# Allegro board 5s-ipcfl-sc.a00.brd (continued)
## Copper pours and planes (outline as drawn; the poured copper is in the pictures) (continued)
VRM_PWM4_SW_C on BOTTOM (solid shape): 61.41,147.55 61.41,147 61.84,146.57 62.99,146.57 63.52,147.09 64.21,147.09 64.59,147.48 69.82,147.48 70.87,146.43 70.87,141.1 68.96,139.19 67.06,139.19 66.8,139.45 66.8,141.1 66.29,141.6 54.94,141.6 54.59,141.95 54.59,142.2 69.98,142.2 69.98,144.8 67.39,144.8 67.39,142.2 54.59,142.2 54.59,147.37 55.07,147.85 61.1,147.85
VRM_PWM4_SW_C on VCC (solid shape): 61.34,148.59 61.34,147.19 61.36,147.1 61.42,147.01 61.8,146.63 61.88,146.58 61.98,146.56 62.87,146.56 62.96,146.58 63.04,146.63 63.86,147.45 69.87,147.45 70.87,146.45 70.87,141.08 68.98,139.19 66.91,139.19 66.8,139.3 66.8,140.97 66.78,141.07 66.73,141.15 66.35,141.53 66.26,141.59 66.17,141.6 54.36,141.6 54.36,148.48 54.59,148.72 61.21,148.72
N27670502 on TOP (solid shape): 64.64,10.29 64.64,6.96 64.14,6.45 64.05,6.45 64.03,6.46 63.48,6.66 62.94,6.45 62.36,6.45 62.05,6.76 62.05,8.31 61.98,8.38 61.98,8.71 62.41,8.71 62.41,9.32 61.98,9.32 61.98,10.54 62.29,10.86 64.07,10.86
N30429432 on TOP (solid shape): 221.39,211.73 221.39,206.4 219.23,204.24 219.23,201.96 218.85,201.57 214.53,201.57 213.77,202.34 211.86,202.34 211.68,202.51 211.68,208.48 214.63,208.48 214.63,210.1 213,210.1 213,208.48 211.68,208.48 211.68,211.56 211.94,211.81 213,211.81 213.01,211.72 213.02,211.64 213.04,211.56 213.06,211.48 213.1,211.41 213.14,211.34 213.19,211.28 213.24,211.21 213.3,211.16 213.37,211.11 213.44,211.07 213.51,211.04 213.59,211.01 213.67,210.99 213.75,210.98 213.83,210.98 213.91,210.98 213.99,211 214.07,211.02 214.14,211.05 214.22,211.08 214.29,211.13 214.35,211.18 214.41,211.23 214.46,211.29 214.51,211.36 214.55,211.43 214.58,211.51 214.6,211.58 214.62,211.66 214.63,211.74 214.63,211.83 214.62,211.91 214.61,211.99 214.58,212.06 214.56,212.14 214.57,212.17 214.58,212.2 214.6,212.22 214.62,212.23 214.66,212.24 220.88,212.24
N30429432 on BOTTOM (solid shape): 219.07,207.52 219.07,201.93 218.69,201.55 214.76,201.55 213.61,202.69 213.61,208.03 213.43,208.21 213.43,208.33 213.49,208.39 214.72,208.39 214.72,210.19 213.06,210.19 213.06,210.41 213.48,210.82 215.77,210.82
N31341317 on TOP (solid shape): outline of 226 points within 156.46,10.41 168.66,17.53
N31341317 on TOP (solid shape): outline of 241 points within 161.54,10.41 168.66,17.53
N31341317 on BOTTOM (solid shape): outline of 241 points within 161.54,10.41 168.66,17.53

Small or netless copper shapes (teardrops, artwork), in the pictures only: 3113 on TOP, 3234 on BOTTOM, 2 on VCC

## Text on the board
BOTTOM: list("[Spacing-SameNet] BOTTOM" "48.Thru Pin to SMD Pin Same Net" "5 MIL [DEFAULT]" "OVERLAP" "" "DRC ERROR CLASS/BOTTOM" "[ThruPin] +12V_CPU (<uTiL>cId3330<uTiL>.1) (2143.9 8555.0)" "[SmdPin] +12V_CPU (<uTiL>cId4743<uTiL>.2) (2182.5 8556.0)" list(2168.000000 8540.000000) nil)@@@list("amy_chou" "2017/07/21 16:08:01" nil "P143000034-PC" "5s-ipcfl-sc.a00")@@@list("iris_chen" "2017/07/24 16:08:43" nil "p16c000357-pc" "5s-ipcfl-sc.a00") | list("[Spacing] BOTTOM" "30.Test Pin to No Probe" "0 MIL [DEFAULT]" "0 MIL" "0.00 MIL" "DRC ERROR CLASS/BOTTOM" "[ThruPin] VRM_PWM2_SW_C (<uTiL>cId2857<uTiL>.1) (2699.14 7688.63)" "[Shape] Manufacturing/No_Probe_Bottom ((2738.19 7647.19) (2851.81 7722.81))" list(2744.140000 7647.190000) nil)@@@list("amy_chou" "2017/07/21 16:05:34" nil "P143000034-PC" "5s-ipcfl-sc.a00")@@@list("iris_chen" "2017/07/24 16:08:08" nil "p16c000357-pc" "5s-ipcfl-sc.a00") | list("[Spacing] BOTTOM" "31.Test Pin to No Probe" "0 MIL [DEFAULT]" "0 MIL" "0.00 MIL" "DRC ERROR CLASS/BOTTOM" "[ThruPin] VRM_PWM1_SW_C (<uTiL>cId2858<uTiL>.1) (2699.14 6995.63)" "[Shape] Manufacturing/No_Probe_Bottom ((2735.19 6962.19) (2848.81 7037.81))" list(2744.140000 6962.190000) nil)@@@list("amy_chou" "2017/07/21 16:05:39" nil "P143000034-PC" "5s-ipcfl-sc.a00")@@@list("iris_chen" "2017/07/24 16:08:09" nil "p16c000357-pc" "5s-ipcfl-sc.a00") | list("[Spacing] BOTTOM" "25.Test Pin to No Probe" "0 MIL [(20)]" "0 MIL" "0.00 MIL" "DRC ERROR CLASS/BOTTOM" "[ThruPin] VRM_PWM3_SW_C (<uTiL>cId2856<uTiL>.1) (2699.14 6302.63)" "[Shape] Manufacturing/No_Probe_Bottom ((2728.19 6262.19) (2841.81 6337.81))" list(2744.140000 6262.190000) nil)@@@list("amy_chou" "2017/07/21 16:05:32" nil "P143000034-PC" "5s-ipcfl-sc.a00")@@@list("iris_chen" "2017/07/24 16:08:01" nil "p16c000357-pc" "5s-ipcfl-sc.a00") | list("[Spacing] BOTTOM" "28.Test Pin to No Probe" "0 MIL [(20)]" "0 MIL" "0.00 MIL" "DRC ERROR CLASS/BOTTOM" "[ThruPin] VRM_PWM4_SW_C (<uTiL>cId2855<uTiL>.1) (2704.14 5649.63)" "[Shape] Manufacturing/No_Probe_Bottom ((2741.19 5612.19) (2854.81 5687.81))" list(2749.140000 5612.190000) nil)@@@list("amy_chou" "2017/07/21 16:05:36" nil "P143000034-PC" "5s-ipcfl-sc.a00")@@@list("iris_chen" "2017/07/24 16:08:05" nil "p16c000357-pc" "5s-ipcfl-sc.a00") | list("[Physical] BOTTOM" "406.Pad/Pad Direct Connect" "NOT_ALLOWED [(PWR_20)]" "ALL_ALLOWED" "" "DRC ERROR CLASS/BOTTOM" "[ThruPin] +VCORE (<uTiL>cId2857<uTiL>.2) (2966.86 7767.37)" "[SmdPin] +VCORE (<uTiL>cId2869<uTiL>.1) (2904.5 7765.0)" list(2904.500000 7765.000000) nil)@@@list("amy_chou" "2017/07/21 16:11:35" nil "P143000034-PC" "5s-ipcfl-sc.a00")@@@list("iris_chen" "2017/07/24 16:23:35" nil "p16c000357-pc" "5s-ipcfl-sc.a00") | list("[Physical] BOTTOM" "408.Pad/Pad Direct Connect" "NOT_ALLOWED [(PWR_20)]" "ALL_ALLOWED" "" "DRC ERROR CLASS/BOTTOM" "[ThruPin] +VCORE (<uTiL>cId2856<uTiL>.2) (2966.86 6381.37)" "[SmdPin] +VCORE (<uTiL>cId332<uTiL>.1) (2905.5 6375.0)" list(2905.500000 6375.000000) nil)@@@list("amy_chou" "2017/07/21 16:11:34" nil "P143000034-PC" "5s-ipcfl-sc.a00")@@@list("iris_chen" "2017/07/24 16:23:37" nil "p16c000357-pc" "5s-ipcfl-sc.a00") | list("[Spacing-SameNet] BOTTOM" "51.Thru Pin to SMD Pin Same Net" "5 MIL [DEFAULT]" "OVERLAP" "" "DRC ERROR CLASS/BOTTOM" "[ThruPin] +VCORE (<uTiL>cId2855<uTiL>.2) (2971.86 5728.37)" "[SmdPin] +VCORE (<uTiL>cId683<uTiL>.1) (2900.5 5729.0)" list(2909.390000 5724.700000) nil)@@@list("amy_chou" "2017/07/21 16:08:03" nil "P143000034-PC" "5s-ipcfl-sc.a00")@@@list("iris_chen" "2017/07/24 16:08:53" nil "p16c000357-pc" "5s-ipcfl-sc.a00") | list("[Physical] BOTTOM" "407.Pad/Pad Direct Connect" "NOT_ALLOWED [(PWR_20)]" "ALL_ALLOWED" "" "DRC ERROR CLASS/BOTTOM" "[ThruPin] +VCORE (<uTiL>cId2858<uTiL>.2) (2966.86 7074.37)" "[SmdPin] +VCORE (<uTiL>cId2871<uTiL>.1) (2915.5 7070.0)" list(2915.500000 7070.000000) nil)@@@list("amy_chou" "2017/07/21 16:11:34" nil "P143000034-PC" "5s-ipcfl-sc.a00")@@@list("iris_chen" "2017/07/24 16:23:36" nil "p16c000357-pc" "5s-ipcfl-sc.a00") | list("[Physical] BOTTOM" "409.Pad/Pad Direct Connect" "NOT_ALLOWED [(PWR_20)]" "ALL_ALLOWED" "" "DRC ERROR CLASS/BOTTOM" "[ThruPin] +1P05V_SA (<uTiL>cId919<uTiL>.1) (3303.0 5378.79)" "[SmdPin] +1P05V_SA (<uTiL>cId329<uTiL>.1) (3306.0 5362.5)" list(3306.000000 5362.500000) nil)@@@list("amy_chou" "2017/07/21 16:11:34" nil "P143000034-PC" "5s-ipcfl-sc.a00")@@@list("iris_chen" "2017/07/24 16:23:38" nil "p16c000357-pc" "5s-ipcfl-sc.a00") | list("[Spacing] BOTTOM" "35.Drill Hole to Drill Hole" "5 MIL [DEFAULT]" "OVERLAP" "" "DRC ERROR CLASS/BOTTOM" "[ThruPin] Dummy (<uTiL>cId1011<uTiL>.3) (3462.78 4855.87)" "[ThruPin] Dummy (<uTiL>cId5049<uTiL>.4) (3462.79 4855.87)" list(3462.780000 4776.370000) nil)@@@list("amy_chou" "2017/07/21 16:05:35" nil "P143000034-PC" "5s-ipcfl-sc.a00")@@@list("iris_chen" "2017/07/24 16:08:13" nil "p16c000357-pc" "5s-ipcfl-sc.a00") | list("[Spacing] BOTTOM" "34.Drill Hole to Drill Hole" "5 MIL [DEFAULT]" "OVERLAP" "" "DRC ERROR CLASS/BOTTOM" "[ThruPin] Dummy (<uTiL>cId1011<uTiL>.2) (3462.78 7808.63)" "[ThruPin] Dummy (<uTiL>cId5049<uTiL>.5) (3462.79 7809.02)" list(3542.260000 7806.790000) nil)@@@list("amy_chou" "2017/07/21 16:05:37" nil "P143000034-PC" "5s-ipcfl-sc.a00")@@@list("iris_chen" "2017/07/24 16:08:12" nil "p16c000357-pc" "5s-ipcfl-sc.a00") | list("[Physical] BOTTOM" "404.Pad/Pad Direct Connect" "NOT_ALLOWED [(PWR_20)]" "ALL_ALLOWED" "" "DRC ERROR CLASS/BOTTOM" "[ThruPin] +VCCGT (<uTiL>cId2854<uTiL>.2) (4066.14 8400.63)" "[SmdPin] +VCCGT (<uTiL>cId2866<uTiL>.1) (4112.5 8424.5)" list(4112.500000 8424.500000) nil)@@@list("amy_chou" "2017/07/21 16:11:37" nil "P143000034-PC" "5s-ipcfl-sc.a00")@@@list("iris_chen" "2017/07/24 16:23:33" nil "p16c000357-pc" "5s-ipcfl-sc.a00") | list("[Spacing-SameNet] BOTTOM" "44.Thru Pin to SMD Pin Same Net" "5 MIL [DEFAULT]" "OVERLAP" "" "DRC ERROR CLASS/BOTTOM" "[ThruPin] VGT_PWM1_SW_C (<uTiL>cId2854<uTiL>.1) (4333.86 8479.37)" "[SmdPin] VGT_PWM1_SW_C (<uTiL>cId2867<uTiL>.1) (4279.5 8429.5)" list(4288.860000 8440.650000) nil)@@@list("amy_chou" "2017/07/21 16:07:58" nil "P143000034-PC" "5s-ipcfl-sc.a00")@@@list("iris_chen" "2017/07/24 16:08:34" nil "p16c000357-pc" "5s-ipcfl-sc.a00") | list("[Spacing] BOTTOM" "29.Drill Hole to Drill Hole" "5 MIL [DEFAULT]" "OVERLAP" "" "DRC ERROR CLASS/BOTTOM" "[ThruPin] Dummy (<uTiL>cId1011<uTiL>.7) (4230.5 7372.21)" "[ThruPin] Dummy (<uTiL>cId5049<uTiL>.2) (4230.51 7372.8)" list(4305.490000 7371.230000) nil)@@@list("amy_chou" "2017/07/21 16:05:37" nil "P143000034-PC" "5s-ipcfl-sc.a00")@@@list("iris_chen" "2017/07/24 16:08:06" nil "p16c000357-pc" "5s-ipcfl-sc.a00") | list("[Physical] BOTTOM" "405.Pad/Pad Direct Connect" "NOT_ALLOWED [(PWR_20)]" "ALL_ALLOWED" "" "DRC ERROR CLASS/BOTTOM" "[ThruPin] +VCCGT (<uTiL>cId2853<uTiL>.2) (4921.14 8400.63)" "[SmdPin] +VCCGT (<uTiL>cId2864<uTiL>.1) (4964.5 8428.5)" list(4964.500000 8428.500000) nil)@@@list("amy_chou" "2017/07/21 16:11:35" nil "P143000034-PC" "5s-ipcfl-sc.a00")@@@list("iris_chen" "2017/07/24 16:23:34" nil "p16c000357-pc" "5s-ipcfl-sc.a00") | list("[Spacing] BOTTOM" "32.Drill Hole to Drill Hole" "5 MIL [DEFAULT]" "OVERLAP" "" "DRC ERROR CLASS/BOTTOM" "[ThruPin] Dummy (<uTiL>cId1011<uTiL>.5) (4939.17 4970.44)" "[ThruPin] Dummy (<uTiL>cId5049<uTiL>.1) (4939.17 4970.44)" list(5014.170000 4970.440000) nil)@@@list("amy_chou" "2017/07/21 16:05:33" nil "P143000034-PC" "5s-ipcfl-sc.a00")@@@list("iris_chen" "2017/07/24 16:08:10" nil "p16c000357-pc" "5s-ipcfl-sc.a00") | list("[Spacing-SameNet] BOTTOM" "45.Thru Pin to SMD Pin Same Net" "4.5 MIL [(20)]" "OVERLAP" "" "DRC ERROR CLASS/BOTTOM" "[ThruPin] VGT_PWM2_SW_C (<uTiL>cId2853<uTiL>.1) (5188.86 8479.37)" "[SmdPin] VGT_PWM2_SW_C (<uTiL>cId2865<uTiL>.1) (5135.5 8426.5)" list(5143.860000 8438.650000) nil)@@@list("amy_chou" "2017/07/21 16:08:01" nil "P143000034-PC" "5s-ipcfl-sc.a00")@@@list("iris_chen" "2017/07/24 16:08:36" nil "p16c000357-pc" "5s-ipcfl-sc.a00") | list("[Spacing-SameNet] BOTTOM" "50.Thru Pin to Thru Pin Same Net" "5 MIL [DEFAULT]" "OVERLAP" "" "DRC ERROR CLASS/BOTTOM" "[ThruPin] GND (<uTiL>cId4700<uTiL>.2) (5645.08 2715.08)" "[ThruPin] GND (<uTiL>cId90<uTiL>.1) (5645.08 2715.08)" list(5679.580000 2715.080000) nil)@@@list("amy_chou" "2017/07/21 16:08:00" nil "P143000034-PC" "5s-ipcfl-sc.a00")@@@list("iris_chen" "2017/07/24 16:08:51" nil "p16c000357-pc" "5s-ipcfl-sc.a00") | list("[Spacing] BOTTOM" "26.Drill Hole to Drill Hole" "5 MIL [DEFAULT]" "OVERLAP" "" "DRC ERROR CLASS/BOTTOM" "[ThruPin] Dummy (<uTiL>cId1011<uTiL>.6) (5647.83 7372.21)" "[ThruPin] Dummy (<uTiL>cId5049<uTiL>.3) (5647.83 7372.8)" list(5722.830000 7372.500000) nil)@@@list("amy_chou" "2017/07/21 16:05:37" nil "P143000034-PC" "5s-ipcfl-sc.a00")@@@list("iris_chen" "2017/07/24 16:08:03" nil "p16c000357-pc" "5s-ipcfl-sc.a00") | list("[Spacing-SameNet] BOTTOM" "47.Thru Pin to Thru Pin Same Net" "5 MIL [DEFAULT]" "OVERLAP" "" "DRC ERROR CLASS/BOTTOM" "[ThruPin] GND (<uTiL>cId4700<uTiL>.1) (5845.08 2715.08)" "[ThruPin] GND (<uTiL>cId90<uTiL>.2) (5845.08 2715.08)" list(5845.080000 2715.080000) nil)@@@list("amy_chou" "2017/07/21 16:07:59" nil "P143000034-PC" "5s-ipcfl-sc.a00")@@@list("iris_chen" "2017/07/24 16:08:42" nil "p16c000357-pc" "5s-ipcfl-sc.a00") | list("[Spacing] BOTTOM" "33.Drill Hole to Drill Hole" "5 MIL [DEFAULT]" "OVERLAP" "" "DRC ERROR CLASS/BOTTOM" "[ThruPin] Dummy (<uTiL>cId1011<uTiL>.1) (6415.55 7808.63)" "[ThruPin] Dummy (<uTiL>cId5049<uTiL>.7) (6415.55 7809.02)" list(6495.050000 7808.820000) nil)@@@list("amy_chou" "2017/07/21 16:05:34" nil "P143000034-PC" "5s-ipcfl-sc.a00")@@@list("iris_chen" "2017/07/24 16:08:11" nil "p16c000357-pc" "5s-ipcfl-sc.a00") | list("[Spacing] BOTTOM" "27.Drill Hole to Drill Hole" "5 MIL [DEFAULT]" "OVERLAP" "" "DRC ERROR CLASS/BOTTOM" "[ThruPin] Dummy (<uTiL>cId1011<uTiL>.4) (6415.55 4855.87)" "[ThruPin] Dummy (<uTiL>cId5049<uTiL>.6) (6415.55 4855.87)" list(6495.050000 4855.870000) nil)@@@list("amy_chou" "2017/07/21 16:05:38" nil "P143000034-PC" "5s-ipcfl-sc.a00")@@@list("iris_chen" "2017/07/24 16:08:04" nil "p16c000357-pc" "5s-ipcfl-sc.a00") | list("[Spacing-SameNet] BOTTOM" "49.Thru Pin to Thru Pin Same Net" "5 MIL [DEFAULT]" "OVERLAP" "" "DRC ERROR CLASS/BOTTOM" "[ThruPin] GND (<uTiL>cId4701<uTiL>.2) (7604.92 1274.92)" "[ThruPin] GND (<uTiL>cId90<uTiL>.3) (7604.92 1274.92)" list(7639.420000 1274.920000) nil)@@@list("amy_chou" "2017/07/21 16:08:00" nil "P143000034-PC" "5s-ipcfl-sc.a00")@@@list("iris_chen" "2017/07/24 16:08:44" nil "p16c000357-pc" "5s-ipcfl-sc.a00") | list("[Spacing-SameNet] BOTTOM" "46.Thru Pin to Thru Pin Same Net" "5 MIL [DEFAULT]" "OVERLAP" "" "DRC ERROR CLASS/BOTTOM" "[ThruPin] GND (<uTiL>cId4701<uTiL>.1) (7804.92 1274.92)" "[ThruPin] GND (<uTiL>cId90<uTiL>.4) (7804.92 1274.92)" list(7804.920000 1274.920000) nil)@@@list("amy_chou" "2017/07/21 16:07:59" nil "P143000034-PC" "5s-ipcfl-sc.a00")@@@list("iris_chen" "2017/07/24 16:08:37" nil "p16c000357-pc" "5s-ipcfl-sc.a00")
